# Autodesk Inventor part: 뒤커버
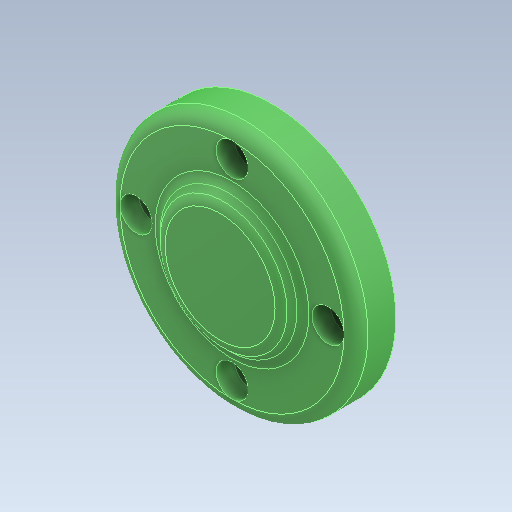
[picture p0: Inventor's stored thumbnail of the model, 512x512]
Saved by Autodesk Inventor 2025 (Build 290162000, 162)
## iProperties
Created: 2024-07
Part Number: 뒤커버
Material: 알루미늄 6061
Document SubType Name: Modeling
Designer: 미서니
Density: 2.71 g/cm^3
Appearance: 기본값
Author: jhkim
Sending System: Autodesk Inventor 2025
Preprocessor: ST-DEVELOPER v20
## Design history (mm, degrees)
feature "솔리드1"
node "솔리드2"
